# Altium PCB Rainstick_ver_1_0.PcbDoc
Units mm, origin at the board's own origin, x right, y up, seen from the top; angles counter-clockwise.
Board outline 87 x 78 mm, 4 copper layers (Top Layer, Internal Plane 1, Internal Plane 2, Bottom Layer); 7 components, 6 nets, 54 pads, 4 vias.
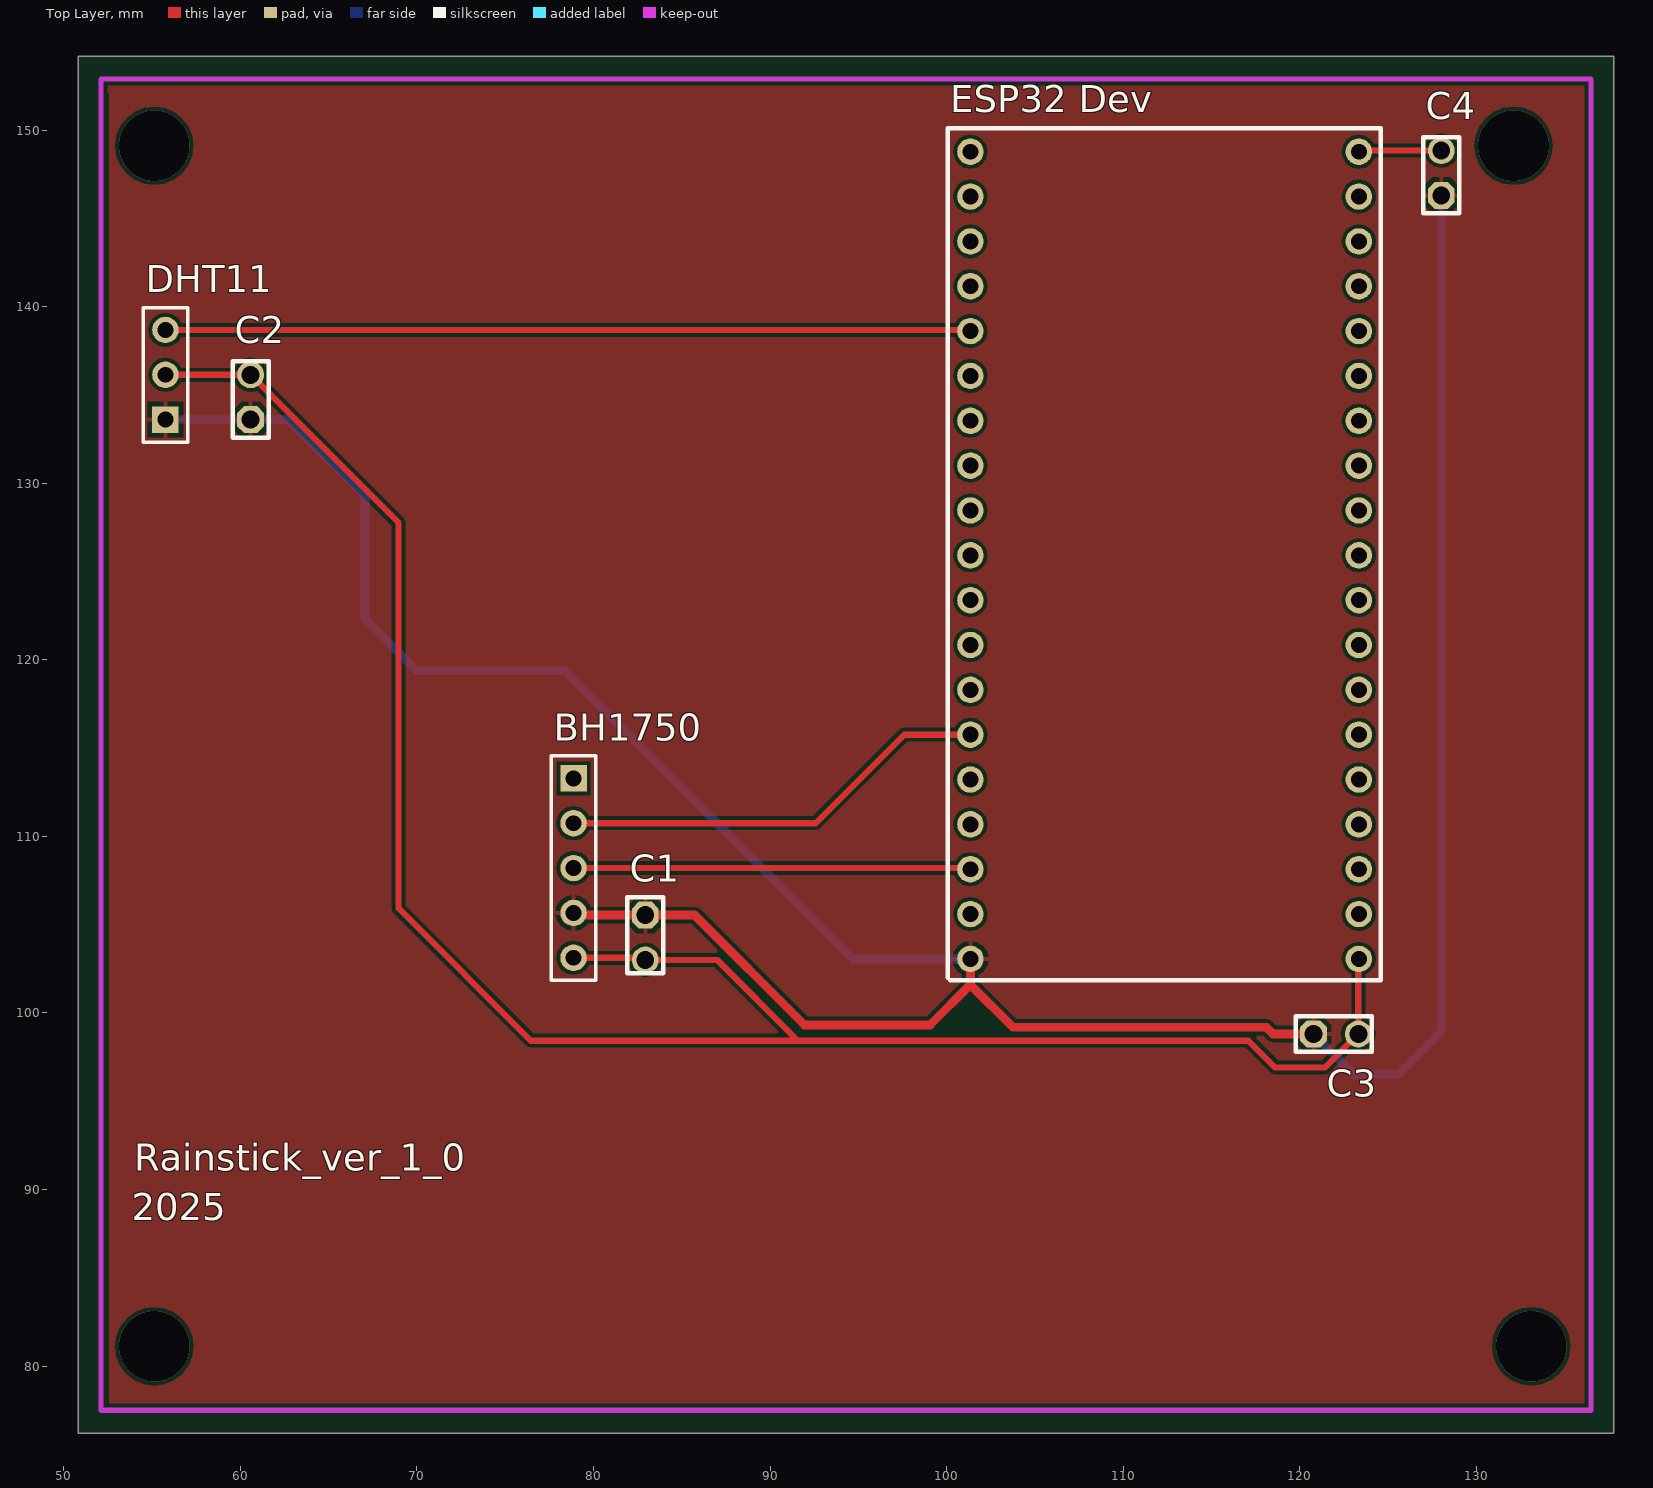
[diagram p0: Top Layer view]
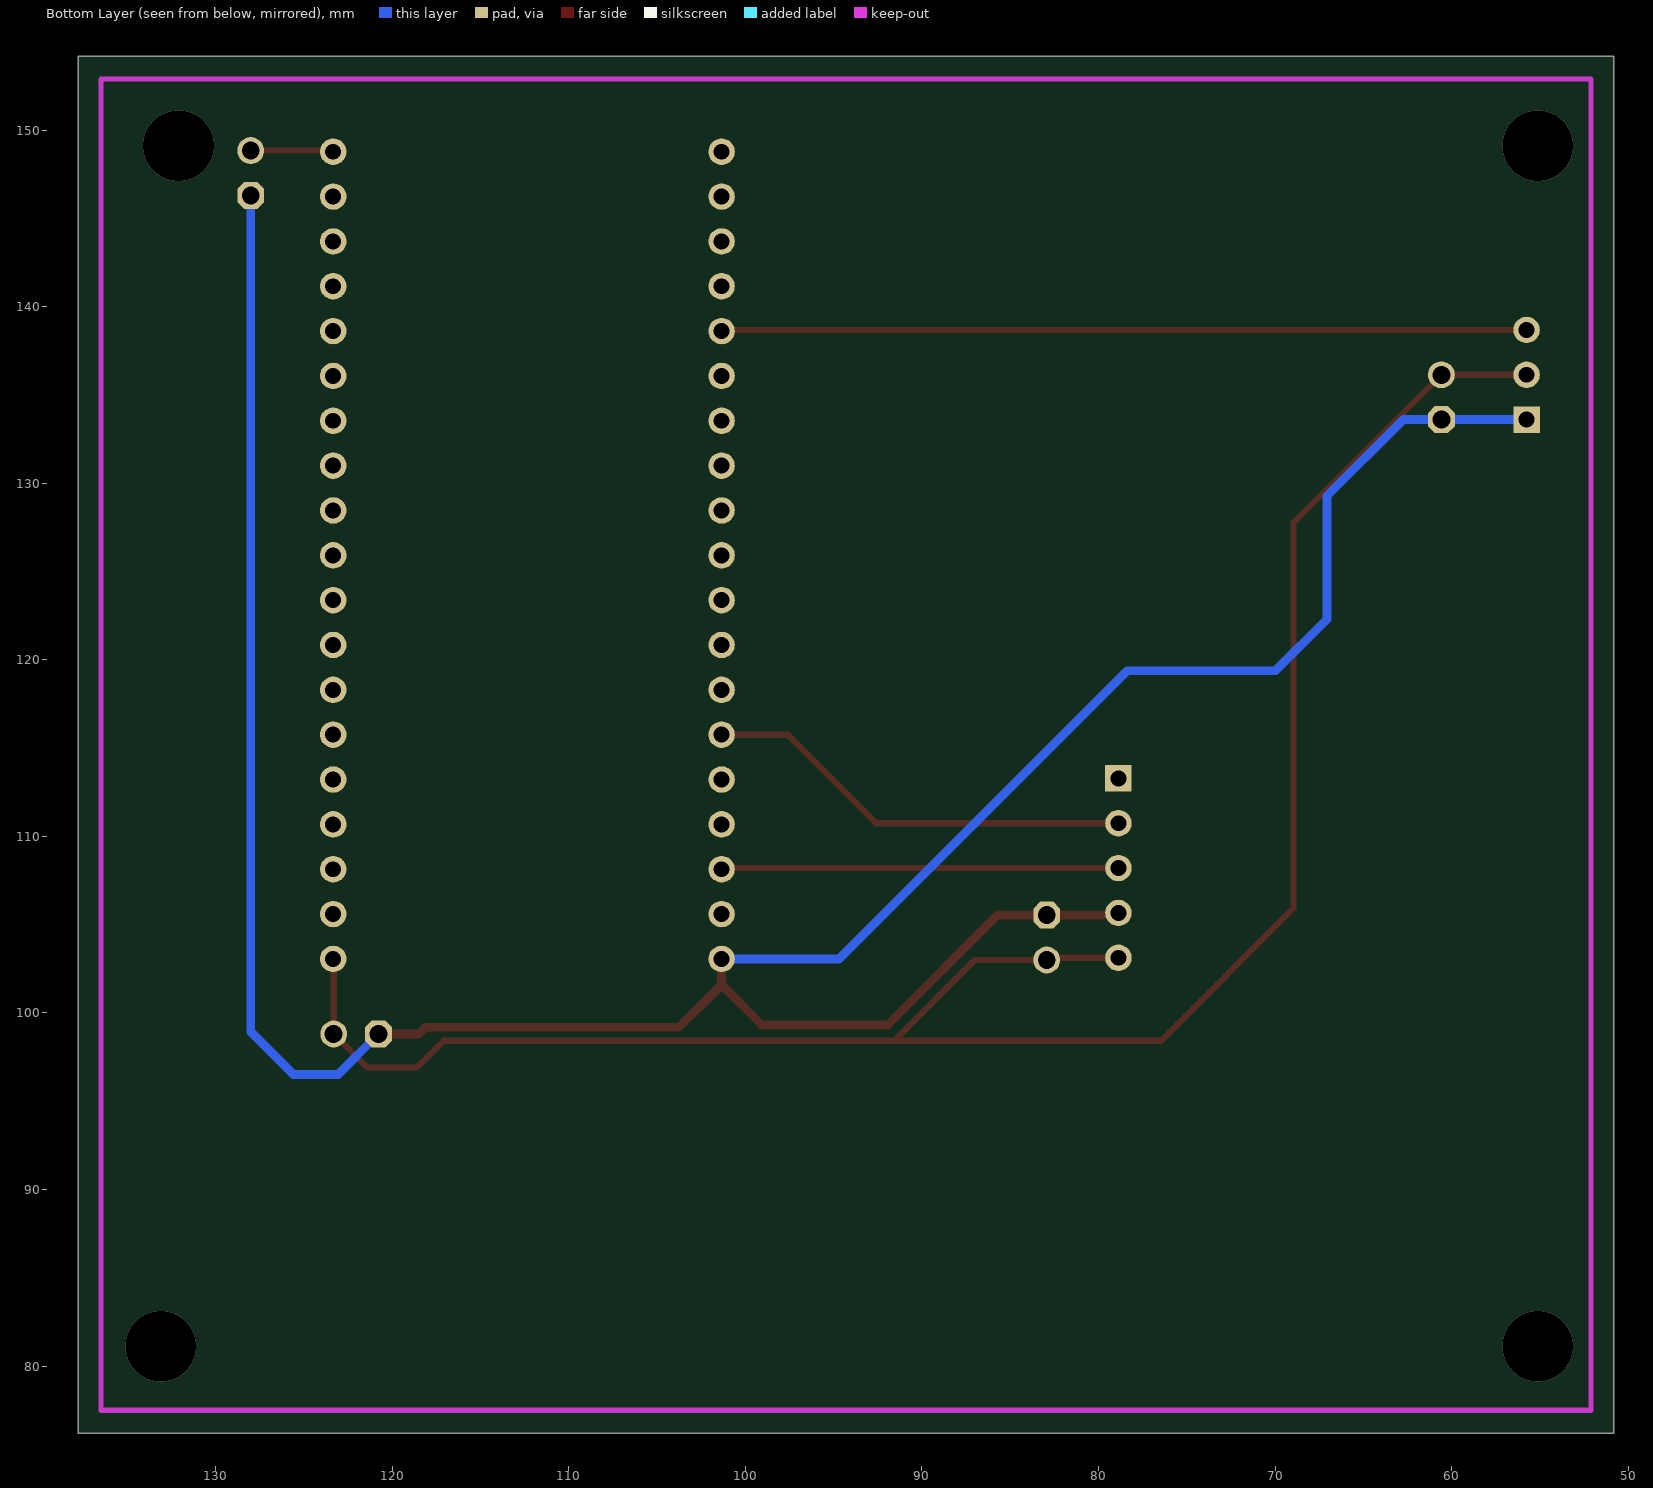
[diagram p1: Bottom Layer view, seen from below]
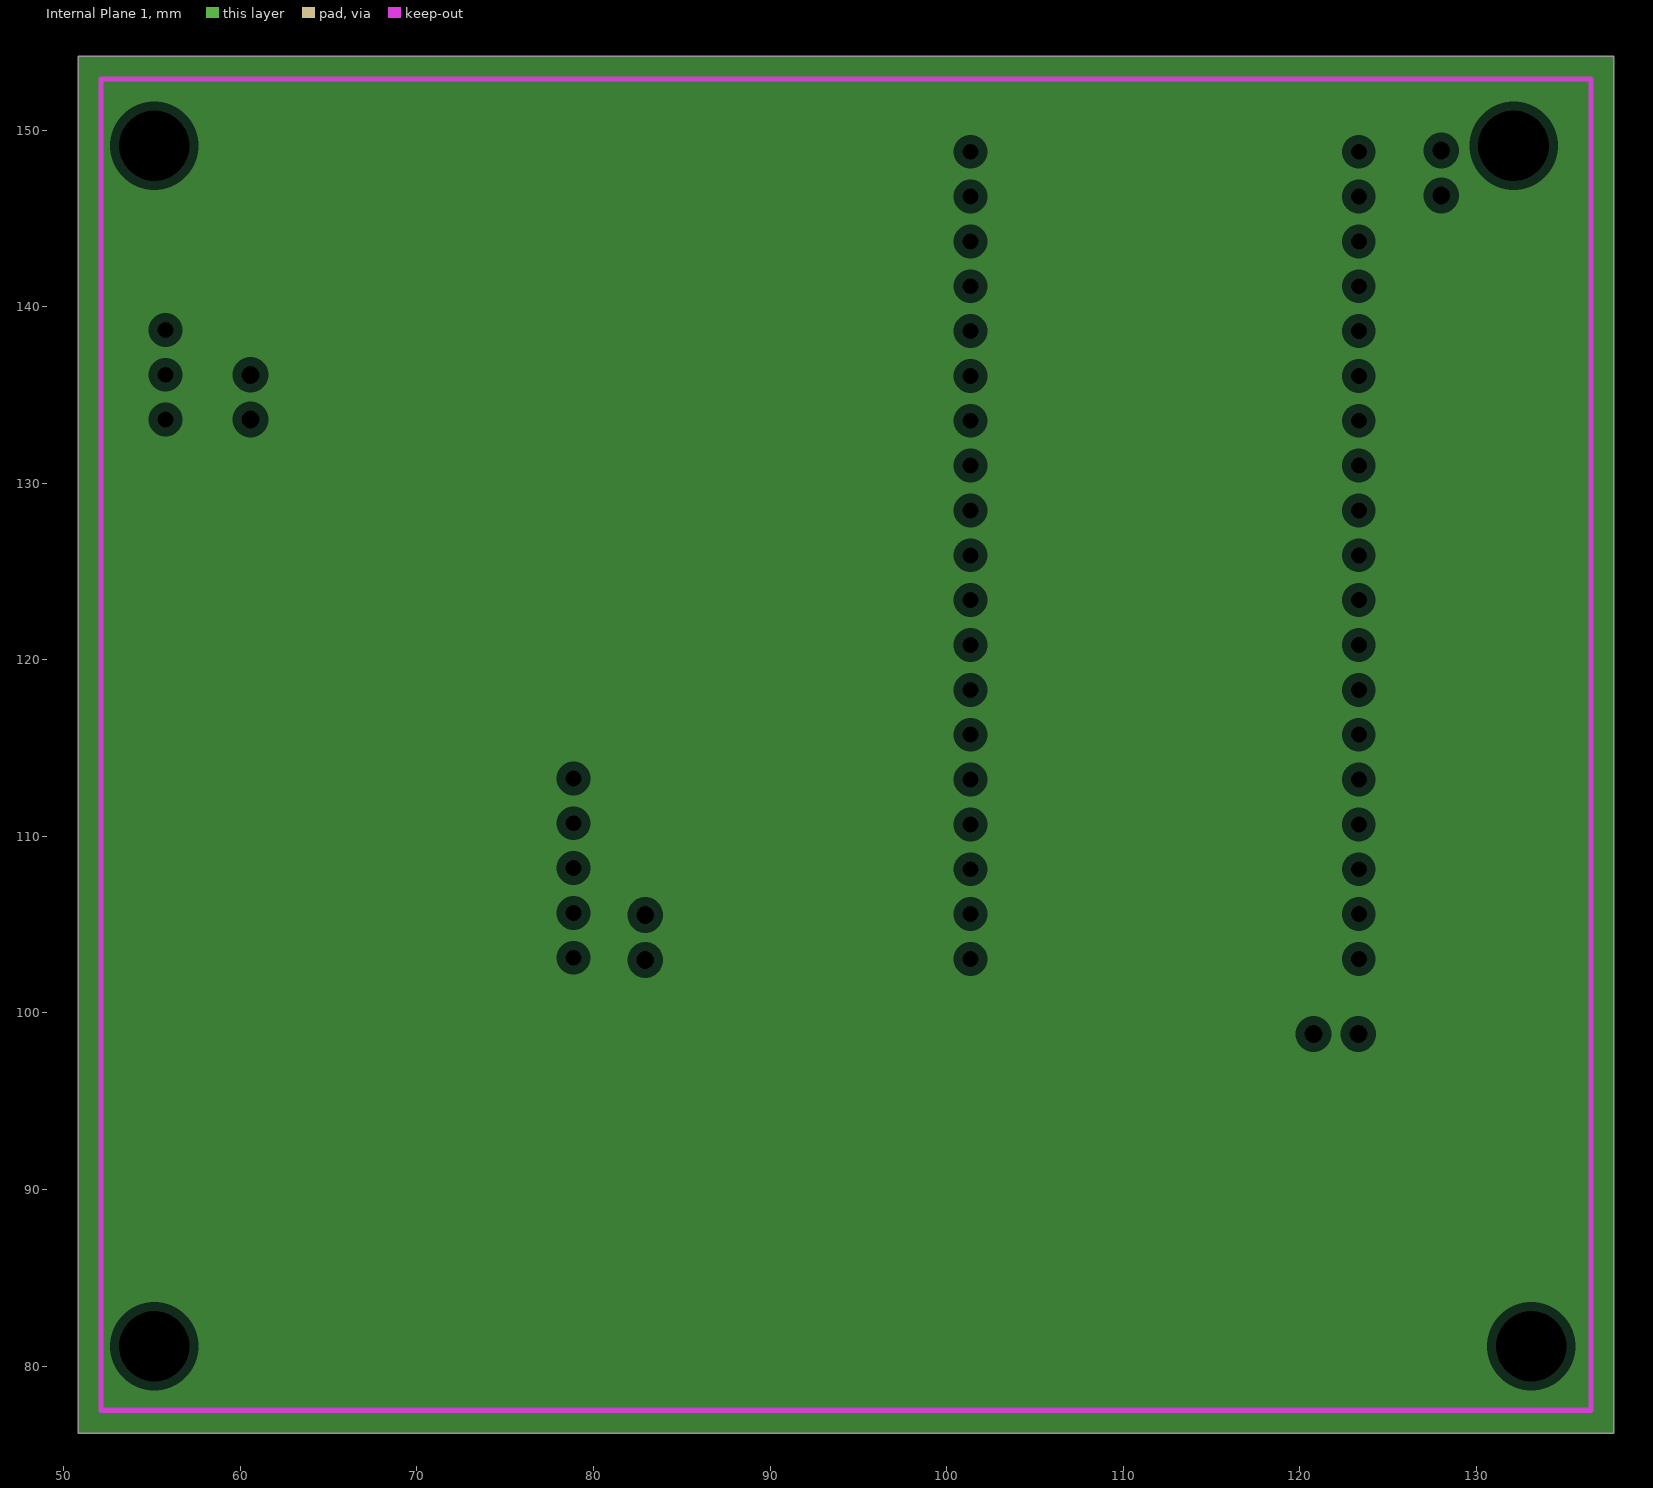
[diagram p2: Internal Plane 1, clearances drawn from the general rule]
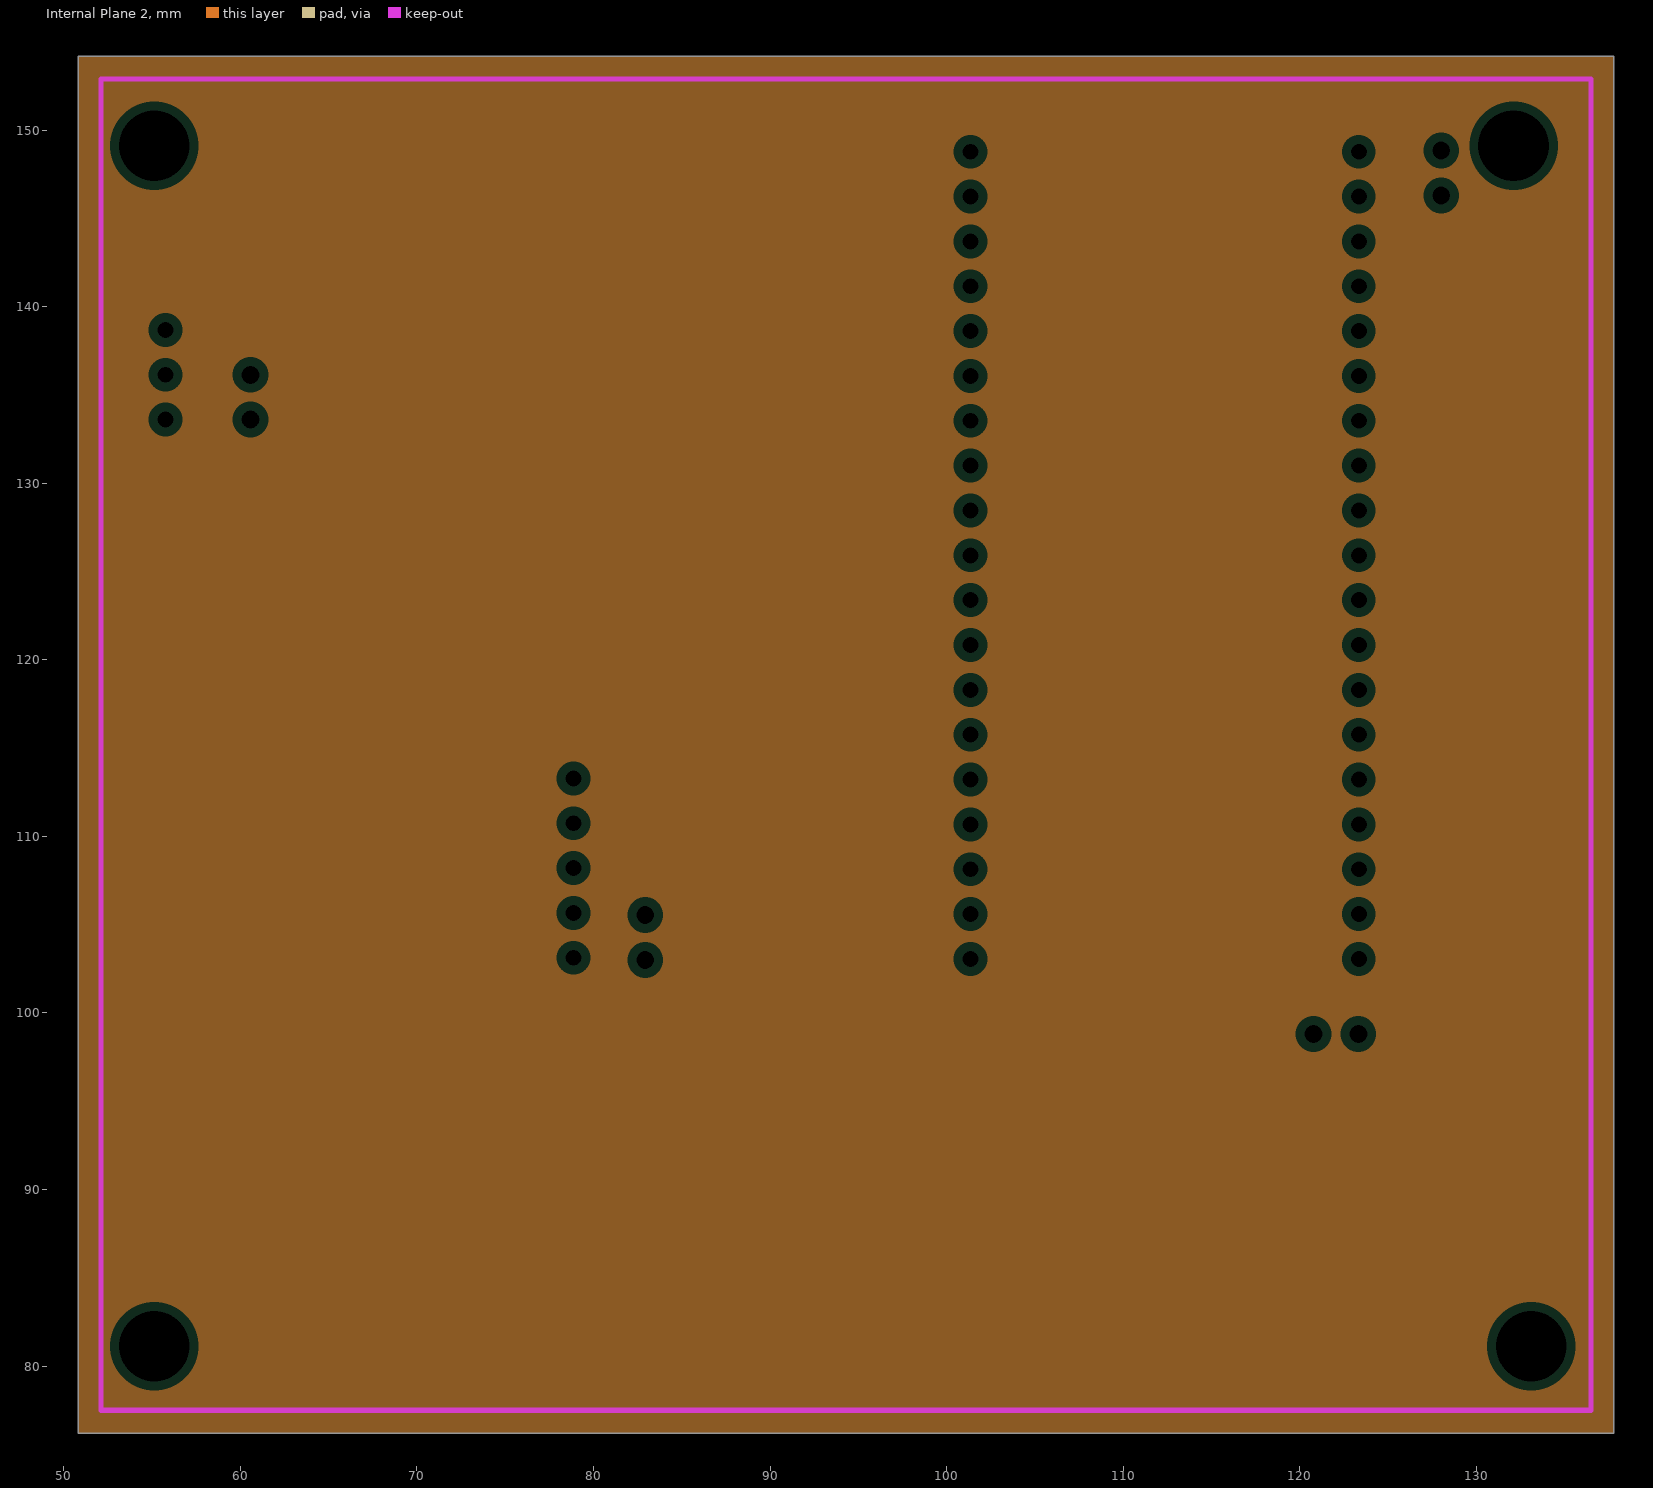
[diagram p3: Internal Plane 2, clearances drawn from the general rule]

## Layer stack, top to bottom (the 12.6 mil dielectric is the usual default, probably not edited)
Top Layer: signal copper 0.0356
Dielectric: dielectric 0.32, FR-4, Dk 4.8
Internal Plane 1: plane copper 0.0356
Dielectric: dielectric 0.32, FR-4, Dk 4.8
Internal Plane 2: plane copper 0.0356
Dielectric: dielectric 0.32, FR-4, Dk 4.8
Bottom Layer: signal copper 0.0356

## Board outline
50.8,76.2 137.8,76.2 137.8,154.2 50.8,154.2

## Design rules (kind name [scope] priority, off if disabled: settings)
Clearance [All] p1: gap=0.2
PlaneClearance [All] p1: clearance=0.508
PlaneConnect [All] p1: planeconnectstyle=Relief reliefexpansion=0.508 reliefentries=4 reliefconductorwidth=0.254 reliefairgap=0.254
PolygonConnect [All] p1: connectstyle=Relief reliefconductorwidth=0.254 reliefentries=4 polygonreliefangle="90 Angle" airgapwidth=0.254
RoomDefinition Rainstick_ver_1_0 [InComponentClass('Rainstick_ver_1_0')] p1: confinementstyle=ConfineIn formatcopy=TRUE lockcomponents=FALSE outline 138.938,77.724 156.337,77.724 156.337,93.472 138.938,93.472
RoutingVias [All] p1: holewidth=0.6 width=1 viastyle="Through Hole" minholewidth=0.711 minwidth=1.27 maxholewidth=0.711 maxwidth=1.27
SolderMaskExpansion [All] p1: expansion=0.102
Width [All] p1: maxlimit=0.2 minlimit=0.2 preferedwidth=0.2
26 further rules are at their usual default settings.

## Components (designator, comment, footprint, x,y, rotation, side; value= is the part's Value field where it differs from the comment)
BH1750 "Header 5" HDR1X5 78.867,113.284 r270 top
C1 "Cap" My_cap100n 82.931,104.267 r270 top
C2 "Cap" My_cap100n 60.579,134.874 r90 top
C3 "Cap" My_cap100n 122.047,98.806 r0 top
C4 "Cap" My_cap100n 128.016,147.574 r90 top
DHT11 "Header 3" HDR1X3 55.753,133.604 r90 top
"ESP32 Dev" "" PCBComponent_1 108.331,136.779 r0 top

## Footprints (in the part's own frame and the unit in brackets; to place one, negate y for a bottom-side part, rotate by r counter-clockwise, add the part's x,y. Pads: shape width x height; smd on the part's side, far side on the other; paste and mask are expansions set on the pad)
HDR1X3 [mm] "Connector; Header; 3 Position"
  rect 1.5x1.5 hole 0.9: 1(0,0)
  round 1.5 hole 0.9: 2(2.54,0) 3(5.08,0)
  silkscreen extent -1.27,-1.27 6.35,1.27
HDR1X5 [mm] "Connector; Header; 5 Position"
  rect 1.5x1.5 hole 0.9: 1(0,0)
  round 1.5 hole 0.9: 2(2.54,0) 3(5.08,0) 4(7.62,0) 5(10.16,0)
  silkscreen extent -1.27,-1.27 11.43,1.27
My_cap100n [mil]
  oct 60x60 hole 40: 1(-50,0)
  round 60 hole 40: 2(50,0)
  silkscreen extent -90,-40 80,40
PCBComponent_1 [mm]
  round 1.5 hole 0.9: 1(-6.985,12) 2(-6.985,9.46) 3(-6.985,6.92) 4(-6.985,4.38) 5(-6.985,1.84) 6(-6.985,-0.7) 7(-6.985,-3.24) 8(-6.985,-5.78) 9(-6.985,-8.32) 10(-6.985,-10.86) 11(-6.985,-13.4) 12(-6.985,-15.94) 13(-6.985,-18.48) 14(-6.985,-21.02) 15(-6.985,-23.56) 16(-6.985,-26.1) 17(-6.985,-28.64) 18(-6.985,-31.18) 19(-6.985,-33.72) 20(15.015,-33.72) 21(15.015,-31.18) 22(15.015,-28.64) 23(15.015,-26.1) 24(15.015,-23.56) 25(15.015,-21.02) 26(15.015,-18.48) 27(15.015,-15.94) 28(15.015,-13.4) 29(15.015,-10.86) 30(15.015,-8.32) 31(15.015,-5.78) 32(15.015,-3.24) 33(15.015,-0.7) 34(15.015,1.84) 35(15.015,4.38) 36(15.015,6.92) 37(15.015,9.46) 38(15.015,12)
  silkscreen extent -8.25,-34.92 16.26,13.33

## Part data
BH1750: "Header, 5-Pin"
C1 C2 C3 C4: library part "Cap ceramic", "CAP-100Nf"
DHT11: "Header, 3-Pin"
"ESP32 Dev": library part Component_1

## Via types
v1: diameter 4, hole 4, Top Layer to Bottom Layer, 4 vias

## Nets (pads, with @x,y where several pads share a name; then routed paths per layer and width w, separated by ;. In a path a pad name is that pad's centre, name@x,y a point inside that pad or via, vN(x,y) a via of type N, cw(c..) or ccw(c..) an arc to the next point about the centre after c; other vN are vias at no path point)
GND: "ESP32 Dev.19" BH1750.4 C1.1 C2.1 C3.1 C4.1 DHT11.1 | length 167
  Top Layer w0.2: BH1750.4 BH1750.4@78.994,105.537 ; 91.948,99.314 92.075,99.314
  Top Layer w0.5: BH1750.4@78.994,105.537 C1.1 85.725,105.537 91.948,99.314 ; 92.075,99.314 99.06,99.314 101.346,101.6 ; 101.346,103.059 101.346,101.6 ; C3.1 118.491,98.806 118.11,99.187 103.759,99.187 101.346,101.6
  Bottom Layer w0.5: DHT11.1 C2.1 62.738,133.604 67.056,129.286 67.056,122.301 69.977,119.38 78.359,119.38 94.68,103.059 101.346,103.059 ; C3.1 123.063,96.52 125.603,96.52 128.016,98.933 C4.1
NetBH1750_2: "ESP32 Dev.14" BH1750.2 | length 24.6
  Top Layer w0.35: BH1750.2 92.583,110.744 97.598,115.759 101.346,115.759
NetBH1750_3: "ESP32 Dev.17" BH1750.3 | length 22.5
  Top Layer w0.2: 101.281,108.204 101.346,108.139
  Top Layer w0.35: BH1750.3 101.281,108.204
NetC4_2: "ESP32 Dev.38" C4.2 | length 4.7
  Top Layer w0.2: 123.346,148.779 123.411,148.844
  Top Layer w0.35: 123.411,148.844 C4.2
NetDHT11_3: "ESP32 Dev.5" DHT11.3 | length 45.6
  Top Layer w0.2: 101.281,138.684 101.346,138.619
  Top Layer w0.35: DHT11.3 101.281,138.684
VCC: "ESP32 Dev.20" BH1750.5 C1.2 C2.2 C3.2 DHT11.2 | length 116.3
  Top Layer w0.2: C1.2@82.804,103.124 C1.2 ; 91.567,98.425 91.694,98.425 ; 123.317,103.03 123.346,103.059
  Top Layer w0.35: DHT11.2 C2.2 68.961,127.762 68.961,122.936 68.961,105.918 76.454,98.425 91.567,98.425 86.995,102.997 C1.2 ; BH1750.5 C1.2@82.804,103.124 ; 91.694,98.425 114.681,98.425 117.094,98.425 118.618,96.901 121.412,96.901 C3.2 123.317,103.03
pads on no net: "ESP32 Dev.1" "ESP32 Dev.2" "ESP32 Dev.3" "ESP32 Dev.4" "ESP32 Dev.6" "ESP32 Dev.7" "ESP32 Dev.8" "ESP32 Dev.9" "ESP32 Dev.10" "ESP32 Dev.11" "ESP32 Dev.12" "ESP32 Dev.13" "ESP32 Dev.15" "ESP32 Dev.16" "ESP32 Dev.18" "ESP32 Dev.21" "ESP32 Dev.22" "ESP32 Dev.23" "ESP32 Dev.24" "ESP32 Dev.25" "ESP32 Dev.26" "ESP32 Dev.27" "ESP32 Dev.28" "ESP32 Dev.29" "ESP32 Dev.30" "ESP32 Dev.31" "ESP32 Dev.32" "ESP32 Dev.33" "ESP32 Dev.34" "ESP32 Dev.35" "ESP32 Dev.36" "ESP32 Dev.37" BH1750.1
copper on no net:
  other v1: 55.118,81.114 133.11,81.114 55.118,149.114 132.11,149.114

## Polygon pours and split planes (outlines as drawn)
GND on Top Layer "Top Layer-No Net" (solid, remove dead copper, pour order 8): 52.1,152.9 136.5,152.9 136.5,77.856 136.144,77.5 52.578,77.5 52.578,152.049 52.1,152.527
no net on Internal Plane 1 (split plane): 137.8,76.2 50.8,76.2 50.8,154.2 137.8,154.2
no net on Internal Plane 2 (split plane): 137.8,76.2 50.8,76.2 50.8,154.2 137.8,154.2

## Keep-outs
Keep-Out Layer:
  lines w0.3: 52.1,77.5 52.1,152.9 136.5,152.9 136.5,77.5 52.1,77.5

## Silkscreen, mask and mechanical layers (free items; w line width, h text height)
Top Overlay:
  text "Rainstick_ver_1_0" at 53.975,91.059 h1.52
  text "2025" at 53.848,88.265 h1.52
Drill Drawing:
  text ".LEGEND" at 142.88,81.28 h1.52
  text "Drill Drawing." at 142.88,78.74 h1.52

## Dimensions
52.1,77.5 to 52.1,152.9 on Mechanical 1
52.1,77.5 to 136.5,77.5 on Mechanical 1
